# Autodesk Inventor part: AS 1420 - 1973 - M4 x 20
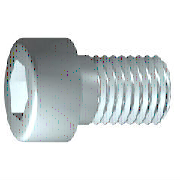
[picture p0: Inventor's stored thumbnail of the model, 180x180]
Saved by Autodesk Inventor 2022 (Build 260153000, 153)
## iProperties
Created: 2021-02
Part Number: AS 1420 - 1973 - M4 x 20
Material: Acciaio, Dolce
Description: Viti con esagono incassato metriche ISO
Document SubType Name: Modeling
Standard: AS 1420 - 1973
Designer: admin
Standards Organization: AS
Language: it-IT
Size Designation: M4 x 20
Categories: <MemberInstance><Categories><Category DisplayName="Elementi di fissaggio" InternalName="e4da775c-781d-43d5-af7c-5136215cf5a6" Mnemonic="FSTN"><Category DisplayN
Density: 7.85 g/cm^3
Appearance: Semilucidato
IsCustomPart: 0
Author: admin
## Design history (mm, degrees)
sketch "Schizzo1"
  geometry: L1 (-1, 0)-(20, 0); L2 (20, 0)-(20, 2); L3 (20, 2)-(6, 2); L4 (6, 2)-(5.57, 2); L5 (5.57, 2)-(0, 2); L6 (0, 2)-(0, 3.5); L7 (0, 3.5)-(-4, 3.5); L8 (-4, 3.5)-(-4, 1.732); L9 (-4, 1.732)-(-2, 1.732); L10 (-2, 1.732)-(-1, 0); L11 (-8.8, 0)-(24.8, 0) reference; L12 (0, -0.7)-(0, 4.2) reference; L13 (6, 2)-(0, 2)
  constraints: 22 end point, 6 parallel, 2 collinear, 2 perpendicular, 1 horizontal, 1 point on line
  dimensions: "d1" = 14 distance from line of L3.end L2 (= GEL); "d2" = 0.42952 distance of L4.end L3.end (computed from GAL); "d3" = 4 distance between parallel lines of L8 L6 (= KOH); "d4" = 2 distance of L8.end L9.end (= INTI); "d5" = 60 deg angle of L10 L1; "d6" = 4 diameter of L3 L1 (= GD); "d7" = 4 diameter of L5 L1 (= BDM); "d8" = 3.4641 diameter of L9 L1 (= 1.1547 x SW); "d9" = 7 diameter of L7 L1 (= KOD); "d26" = 20 distance between parallel lines of L12 L2 (= NLG)
revolve "Corpo" sketch "Schizzo1" stored, may be unused: angle "d10" = 90 deg
sketch "Schizzo2"
  geometry: L1 (0, -4.9)-(0, 4.9) reference; L2 (-4.9, 0)-(4.9, 0) reference; L3 (1.732, 0)-(0.866, -1.5); L4 (0.866, -1.5)-(-0.866, -1.5); L5 (-0.866, -1.5)-(-1.732, 0); L6 (-1.732, 0)-(-0.866, 1.5); L7 (-0.866, 1.5)-(0.866, 1.5); L8 (0.866, 1.5)-(1.732, 0); 2 further points
  constraints: 12 end point, 1 coincident, 1 horizontal alignment, 1 point on line, 12 other
extrude "Intaglio" join sketch "Schizzo2" stored distance "d11" = 10; taper "d12" = 0 deg
workplane "Work Plane1"
fillet "Fillet2" dims "d30" = 0.1 (= R)
body "Solid1"
fillet "Raccordo1" dims "d17" = 0.4 (= RR)
feature "Filettatura" dims "d13" = 14 (= GEL), "d14" = 0
chamfer "Smusso1" distance "d15" = 0.42941 (= -0.5 x SPD + 0.5 x GD); stored, may be unused: second distance "d16" = 0.42941 (= GUL), angle "d27" = 45 deg
other parameters: "GD" = 4 (= NND) [user parameter; used in 2 equation terms], "NLG" = 20 [user parameter; used in 1 equation term], "GEL" = 14 [user parameter; used in 2 equation terms], "KOD" = 7 [user parameter; used in 1 equation term], "KOH" = 4 (= NND) [user parameter; used in 1 equation term], "INTI" = 2 [user parameter; used in 1 equation term], "GAL" = 0.42941 (= 0.61345 x PTC) [user parameter; used in 1 equation term], "GUL" = 0.42941 (= 0.61345 x PTC) [user parameter; used in 1 equation term], "BDM" = 4 (= NND) [user parameter; used in 1 equation term], "SW" = 3 [user parameter; used in 2 equation terms], "RR" = 0.4 (= 0.1 x NND) [user parameter; used in 1 equation term], "SPD" = 3.14117 (= NND - 1.2269 x PTC) [user parameter; used in 1 equation term], "d19" = 0, "d28" = 0, "d29" = 0, "R" = 0.1 [user parameter; used in 1 equation term], "PHH" = 0.13 [user parameter], "GD1" = 3.14117 (= THREADDIA - 1.2269 x PTC) [user parameter], "THREADDIA" = 4 [user parameter; used in 1 equation term], "FAWI" = 45 deg [user parameter], "TPU" = 14.28571 (computed from PTC) [user parameter], "PTC" = 0.7 [user parameter; used in 5 equation terms], "KOH1" = 3.6 [user parameter], "NND" = 4 [user parameter; used in 5 equation terms], "TOA" = 30 deg [user parameter], "E0" = 3.465 (= 1.155 x SW) [user parameter]
